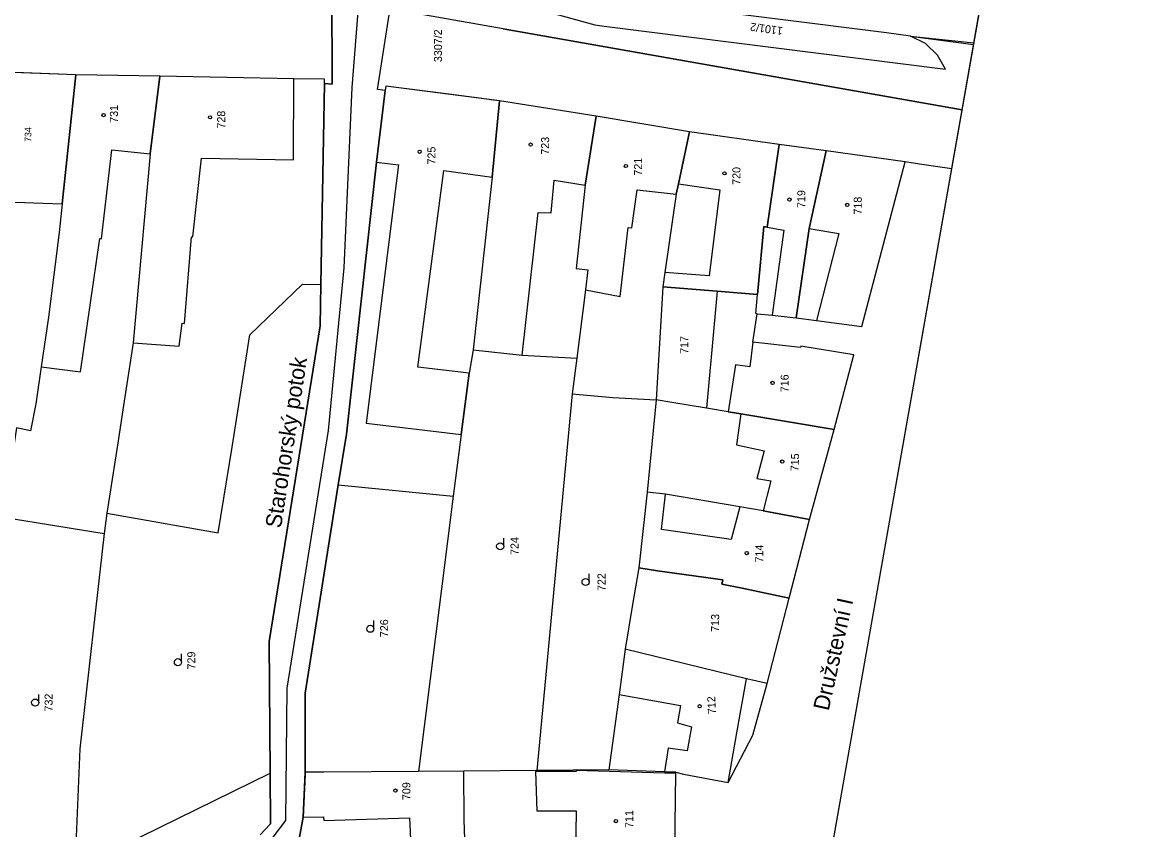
# Model space of a CAD drawing. Extents: x -534481 to -534262, y -1190577 to -1190138.
# Drawn here: x -534379.7 to -534261.7, y -1190343.4 to -1190257.6 of the extents above; entities that cross this region are included whole.
import ezdxf

# ---------------------------------------------------------------- set-up
doc = ezdxf.new("R2010")
doc.units = 0
for name, color, linetype in [('_KN_Povodí_Moravy', 7, 'Continuous'), ('_N_osa', 7, 'Continuous'), ('_rámeček', 7, 'Continuous'), ('_rámeček_mřížka', 7, 'Continuous'), ('Hranice parcel', 7, 'Continuous'), ('Parcelní čísla', 7, 'Continuous'), ('Polygon budovy', 7, 'Continuous'), ('Pop  PČ popisy', 7, 'Continuous'), ('Značky budov', 7, 'Continuous'), ('Značky kultur', 7, 'Continuous')]:
    doc.layers.add(name, color=color, linetype=linetype)

msp = doc.modelspace()

# ---------------------------------------------------------------- linework, layer by layer
at = {"layer": '_KN_Povodí_Moravy'}
msp.add_line((-534347.63, -1190264.06), (-534348.02, -1190285.43), dxfattribs=at)
for points in [[(-534346.75, -1190251.25), (-534346.86, -1190254.17), (-534346.83, -1190264.15), (-534347.63, -1190264.06)], [(-534341.18, -1190264.8), (-534341.99, -1190264.71), (-534340.47, -1190254.93), (-534340.33, -1190252.09)], [(-534346.16, -1190306.72), (-534345.3, -1190301.34), (-534342.09, -1190272.42), (-534341.18, -1190264.8)], [(-534348.02, -1190285.43), (-534348.1, -1190289.81), (-534353.51, -1190323.36), (-534353.4, -1190337.34)], [(-534349.69, -1190337.24), (-534349.7, -1190328.83), (-534346.16, -1190306.72)], [(-534353.09, -1190348.56), (-534350.53, -1190345.48), (-534349.9, -1190342.02), (-534349.69, -1190337.24)], [(-534353.4, -1190337.34), (-534353.36, -1190342.74), (-534354.46, -1190343.91)]]:
    msp.add_lwpolyline(points, dxfattribs=at)
at = {"layer": '_N_osa'}
for points in [[(-534344.68, -1190264.49), (-534342.94, -1190242.55)], [(-534409.87, -1190391.44), (-534405.95, -1190382.82), (-534400.87, -1190377.49), (-534393.7, -1190372.72), (-534384.93, -1190365.48), (-534382.63, -1190361.15), (-534355.89, -1190347.82), (-534351.74, -1190342.39), (-534351.58, -1190328.32), (-534347.2, -1190300.92), (-534345.55, -1190283.64), (-534344.68, -1190264.49)]]:
    msp.add_lwpolyline(points, dxfattribs=at)
at = {"layer": '_rámeček'}
for p, q in [((-534279.9, -1190266.87), (-534261.67, -1190163.46)), ((-534298.13, -1190370.27), (-534279.9, -1190266.87))]:
    msp.add_line(p, q, dxfattribs=at)
for points in [[(-534407.91, -1190137.67), (-534480.84, -1190551.29), (-534334.6, -1190577.08), (-534261.67, -1190163.46)], [(-534328.65, -1190258.27), (-534426.15, -1190241.08), (-534444.38, -1190344.48), (-534298.13, -1190370.27)], [(-534328.65, -1190258.27), (-534279.9, -1190266.87)], [(-534279.9, -1190266.87), (-534328.65, -1190258.27)]]:
    msp.add_lwpolyline(points, dxfattribs=at)
at = {"layer": '_rámeček_mřížka'}
msp.add_line((-534282.86, -1190266.34), (-534279.9, -1190266.87), dxfattribs=at)
msp.add_lwpolyline([(-534480.84, -1190551.29), (-534334.6, -1190577.08), (-534261.67, -1190163.46)], dxfattribs=at)
at = {"layer": 'Hranice parcel'}
for p, q in [((-534374.06, -1190263.13), (-534382.71, -1190262.81)), ((-534365.11, -1190263.3), (-534374.06, -1190263.13)), ((-534348.02, -1190285.43), (-534347.63, -1190264.06)), ((-534318.76, -1190267.54), (-534329.03, -1190265.92)), ((-534308.86, -1190269.19), (-534318.76, -1190267.54)), ((-534299.34, -1190270.54), (-534308.86, -1190269.19)), ((-534294.34, -1190271.21), (-534299.34, -1190270.54)), ((-534285.95, -1190272.39), (-534294.34, -1190271.21)), ((-534311.69, -1190285.66), (-534312.39, -1190297.68)), ((-534305.91, -1190286.14), (-534311.69, -1190285.66)), ((-534305.91, -1190286.14), (-534306.23, -1190289.63)), ((-534301.62, -1190286.49), (-534305.91, -1190286.14)), ((-534306.23, -1190289.63), (-534307.05, -1190298.57)), ((-534321.31, -1190297.03), (-534325.09, -1190337.06)), ((-534312.39, -1190297.68), (-534313.35, -1190307.49)), ((-534296.1, -1190310.4), (-534293.5, -1190300.81)), ((-534346.16, -1190306.72), (-534333.95, -1190307.91)), ((-534313.35, -1190307.49), (-534314.25, -1190315.51)), ((-534333.95, -1190307.91), (-534337.65, -1190337.15)), ((-534370.75, -1190309.73), (-534371.05, -1190311.86)), ((-534381.75, -1190310.15), (-534371.05, -1190311.86)), ((-534298.26, -1190318.76), (-534296.1, -1190310.4)), ((-534300.61, -1190327.81), (-534298.26, -1190318.76)), ((-534332.83, -1190337.12), (-534337.65, -1190337.15)), ((-534325.09, -1190337.06), (-534332.83, -1190337.12)), ((-534317.41, -1190337), (-534325.09, -1190337.06)), ((-534374.14, -1190347.51), (-534353.4, -1190337.34))]:
    msp.add_line(p, q, dxfattribs=at)
for points in [[(-534347.63, -1190264.06), (-534346.83, -1190264.15), (-534346.86, -1190254.17), (-534346.75, -1190251.25)], [(-534341.18, -1190264.8), (-534341.99, -1190264.71), (-534340.47, -1190254.93), (-534340.33, -1190252.09)], [(-534328.28, -1190255.25), (-534318.9, -1190257.84), (-534317.93, -1190257.96), (-534281.65, -1190262.55), (-534282.51, -1190261.06), (-534283.8, -1190259.83), (-534285.39, -1190259.03)], [(-534285.39, -1190259.03), (-534287.93, -1190258.69), (-534311.1, -1190255.76)], [(-534285.39, -1190259.03), (-534278.68, -1190259.92)], [(-534285.39, -1190259.03), (-534278.65, -1190259.74)], [(-534374.06, -1190263.13), (-534375.5, -1190276.84), (-534375.82, -1190279.89), (-534376.96, -1190288.9), (-534377.73, -1190294.18), (-534378.22, -1190297.6), (-534378.27, -1190297.93), (-534378.86, -1190300.97), (-534380.33, -1190300.65), (-534380.94, -1190304.74), (-534381.36, -1190307.53), (-534381.75, -1190310.15)], [(-534365.11, -1190263.3), (-534366.14, -1190271.54), (-534367.96, -1190291.63), (-534368.98, -1190298.28), (-534369.63, -1190302.5), (-534370.75, -1190309.73)], [(-534347.63, -1190264.06), (-534347.63, -1190263.6), (-534350.88, -1190263.57), (-534365.11, -1190263.3)], [(-534341.18, -1190264.8), (-534342.09, -1190272.42), (-534345.3, -1190301.34), (-534346.16, -1190306.72)], [(-534329.03, -1190265.92), (-534341.12, -1190264.34), (-534341.18, -1190264.8)], [(-534329.03, -1190265.92), (-534329.83, -1190274.01), (-534331.85, -1190292.36)], [(-534329.03, -1190265.92), (-534330.01, -1190265.79)], [(-534318.76, -1190267.54), (-534319.95, -1190274.86), (-534320.89, -1190283.73), (-534319.66, -1190283.86), (-534319.92, -1190285.99), (-534320.83, -1190293.25)], [(-534308.86, -1190269.19), (-534310.04, -1190274.74), (-534310.28, -1190275.84), (-534311.47, -1190284.16), (-534311.69, -1190285.66)], [(-534299.34, -1190270.54), (-534300.62, -1190279.32), (-534300.98, -1190279.26), (-534301.62, -1190286.49)], [(-534294.34, -1190271.21), (-534296.16, -1190279.48), (-534297.54, -1190288.96)], [(-534297.54, -1190288.96), (-534295.37, -1190289.25), (-534290.54, -1190289.89), (-534285.95, -1190272.39)], [(-534281.01, -1190273.14), (-534282, -1190272.99), (-534284.44, -1190272.62), (-534285.95, -1190272.39)], [(-534370.75, -1190309.73), (-534358.94, -1190311.81), (-534357.43, -1190302.69), (-534355.55, -1190290.76), (-534349.96, -1190285.37), (-534348.02, -1190285.43)], [(-534353.4, -1190337.34), (-534353.51, -1190323.36), (-534348.1, -1190289.81), (-534348.02, -1190285.43)], [(-534301.66, -1190288.52), (-534301.8, -1190288.5), (-534301.62, -1190286.49)], [(-534293.5, -1190300.81), (-534291.39, -1190292.89), (-534297.04, -1190291.98), (-534297.07, -1190292.12), (-534302.14, -1190291.55), (-534301.66, -1190288.52)], [(-534301.66, -1190288.52), (-534300.07, -1190288.69), (-534297.54, -1190288.96)], [(-534331.85, -1190292.36), (-534332.25, -1190294.85), (-534333.12, -1190301.37), (-534333.95, -1190307.91)], [(-534331.85, -1190292.36), (-534326.64, -1190292.92), (-534320.83, -1190293.25)], [(-534320.83, -1190293.25), (-534320.97, -1190294.31), (-534321.31, -1190297.03)], [(-534321.31, -1190297.03), (-534317.01, -1190297.41), (-534312.39, -1190297.68)], [(-534307.05, -1190298.57), (-534310.73, -1190297.96), (-534312.39, -1190297.68)], [(-534293.5, -1190300.81), (-534303.4, -1190299.17), (-534304.76, -1190298.94), (-534307.05, -1190298.57)], [(-534346.16, -1190306.72), (-534349.7, -1190328.83), (-534349.69, -1190337.24)], [(-534296.1, -1190310.4), (-534301.05, -1190309.46), (-534303.52, -1190309.04), (-534311.4, -1190307.7), (-534313.35, -1190307.49)], [(-534371.05, -1190311.86), (-534373.6, -1190334.76), (-534374.14, -1190347.51)], [(-534314.25, -1190315.51), (-534314.94, -1190319.65), (-534315.69, -1190324.17)], [(-534298.26, -1190318.76), (-534303.28, -1190317.7), (-534305.42, -1190317.25), (-534305.33, -1190316.8), (-534312.25, -1190315.85), (-534314.25, -1190315.51)], [(-534315.69, -1190324.17), (-534316.34, -1190328.99), (-534317.41, -1190337)], [(-534300.61, -1190327.81), (-534302.8, -1190327.32), (-534315.69, -1190324.17)], [(-534310.32, -1190337.25), (-534309.51, -1190337.45), (-534304.75, -1190338.32), (-534302.13, -1190333.32), (-534300.61, -1190327.81)], [(-534349.69, -1190337.24), (-534349.69, -1190337.44), (-534349.9, -1190342.02), (-534350.53, -1190345.48), (-534353.09, -1190348.56)], [(-534337.65, -1190337.15), (-534347.69, -1190337.23), (-534349.69, -1190337.24)], [(-534332.53, -1190349.48), (-534332.78, -1190342.31), (-534332.83, -1190337.12)], [(-534310.32, -1190337.25), (-534311.5, -1190337.21), (-534317.41, -1190337)], [(-534315.73, -1190352.48), (-534310.81, -1190348.3), (-534310.45, -1190348.3), (-534310.32, -1190337.38), (-534310.32, -1190337.25)], [(-534354.46, -1190343.91), (-534353.36, -1190342.74), (-534353.4, -1190337.34)]]:
    msp.add_lwpolyline(points, dxfattribs=at)
at = {"layer": 'Polygon budovy'}
for points in [[(-534382.71, -1190262.81), (-534383.47, -1190268.46), (-534384.56, -1190276.52), (-534375.5, -1190276.84), (-534374.06, -1190263.13)], [(-534377.73, -1190294.18), (-534373.53, -1190294.69), (-534371.48, -1190280.54), (-534371.33, -1190280.57), (-534370.23, -1190271.12), (-534366.14, -1190271.54), (-534365.11, -1190263.3), (-534374.06, -1190263.13), (-534375.5, -1190276.84), (-534375.82, -1190279.89), (-534376.96, -1190288.9)], [(-534366.14, -1190271.54), (-534367.96, -1190291.63), (-534363.08, -1190291.98), (-534362.74, -1190289.52), (-534362.49, -1190289.56), (-534361.74, -1190280.34), (-534361.6, -1190280.35), (-534360.7, -1190271.99), (-534350.93, -1190272.19), (-534350.88, -1190263.57), (-534365.11, -1190263.3)], [(-534329.03, -1190265.92), (-534329.83, -1190274.01), (-534331.85, -1190292.36), (-534326.64, -1190292.92), (-534324.94, -1190277.76), (-534323.57, -1190277.82), (-534323.23, -1190274.35), (-534319.95, -1190274.86), (-534318.76, -1190267.54)], [(-534319.92, -1190285.99), (-534316.22, -1190286.71), (-534315.36, -1190279.35), (-534314.97, -1190279.41), (-534314.43, -1190275.35), (-534310.28, -1190275.84), (-534310.04, -1190274.74), (-534308.86, -1190269.19), (-534318.76, -1190267.54), (-534319.95, -1190274.86), (-534320.89, -1190283.73), (-534319.66, -1190283.86)], [(-534311.69, -1190285.66), (-534305.91, -1190286.14), (-534301.62, -1190286.49), (-534300.98, -1190279.26), (-534300.62, -1190279.32), (-534299.34, -1190270.54), (-534308.86, -1190269.19), (-534310.04, -1190274.74), (-534305.65, -1190275.36), (-534306.77, -1190284.49), (-534311.47, -1190284.16)], [(-534300.07, -1190288.69), (-534297.54, -1190288.96), (-534296.16, -1190279.48), (-534294.34, -1190271.21), (-534299.34, -1190270.54), (-534300.62, -1190279.32), (-534298.85, -1190279.64)], [(-534295.37, -1190289.25), (-534290.54, -1190289.89), (-534285.95, -1190272.39), (-534294.34, -1190271.21), (-534296.16, -1190279.48), (-534293, -1190280.01)], [(-534302.14, -1190291.55), (-534302.44, -1190294.18), (-534303.96, -1190293.94), (-534304.76, -1190298.94), (-534303.4, -1190299.17), (-534293.5, -1190300.81), (-534291.39, -1190292.89), (-534297.04, -1190291.98), (-534297.07, -1190292.12)], [(-534301.7, -1190306.03), (-534300.21, -1190306.28), (-534301.05, -1190309.46), (-534296.1, -1190310.4), (-534293.5, -1190300.81), (-534303.4, -1190299.17), (-534303.85, -1190302.47), (-534300.92, -1190303.1)], [(-534314.25, -1190315.51), (-534312.25, -1190315.85), (-534305.33, -1190316.8), (-534305.42, -1190317.25), (-534303.28, -1190317.7), (-534298.26, -1190318.76), (-534296.1, -1190310.4), (-534301.05, -1190309.46), (-534303.52, -1190309.04), (-534304.43, -1190312.52), (-534311.84, -1190311.46), (-534311.4, -1190307.7), (-534313.35, -1190307.49)], [(-534310.13, -1190332), (-534308.64, -1190332.42), (-534309.09, -1190334.97), (-534311.12, -1190334.7), (-534311.5, -1190337.21), (-534310.32, -1190337.25), (-534309.51, -1190337.45), (-534304.75, -1190338.32), (-534303.82, -1190333.06), (-534302.8, -1190327.32), (-534315.69, -1190324.17), (-534316.34, -1190328.99), (-534309.81, -1190330.15)], [(-534349.9, -1190342.02), (-534347.72, -1190341.99), (-534347.71, -1190342.39), (-534338.59, -1190342.1), (-534338.12, -1190352.66), (-534336.88, -1190352.6), (-534336.67, -1190354.99), (-534334.35, -1190354.21), (-534332.65, -1190353.81), (-534332.6, -1190352.16), (-534332.53, -1190349.48), (-534332.78, -1190342.31), (-534332.83, -1190337.12), (-534337.65, -1190337.15), (-534347.69, -1190337.23), (-534349.69, -1190337.24), (-534349.69, -1190337.44)], [(-534320.89, -1190337.07), (-534320.88, -1190337.18), (-534325.2, -1190337.17), (-534325.09, -1190341.34), (-534320.9, -1190341.35), (-534320.99, -1190348.17), (-534318.18, -1190348.21), (-534317.67, -1190349.12), (-534315.85, -1190349.15), (-534315.3, -1190348.25), (-534310.81, -1190348.3), (-534310.45, -1190348.3), (-534310.32, -1190337.38)]]:
    msp.add_lwpolyline(points, close=True, dxfattribs=at)
msp.add_lwpolyline([(-534334.43, -1190265.21), (-534341.12, -1190264.34), (-534341.18, -1190264.8), (-534342.09, -1190272.42), (-534339.77, -1190272.69), (-534343.2, -1190300.17), (-534333.12, -1190301.37), (-534332.25, -1190294.85), (-534337.72, -1190294.22), (-534334.94, -1190273.31), (-534329.83, -1190274.01), (-534329.03, -1190265.92), (-534334.43, -1190265.21)], dxfattribs=at)
at = {"layer": 'Značky budov'}
for centre in [(-534371.09, -1190267.42), (-534359.79, -1190267.66), (-534337.52, -1190271.32), (-534325.73, -1190270.56), (-534315.62, -1190272.83), (-534305.15, -1190273.61), (-534298.25, -1190276.39), (-534292.11, -1190276.96), (-534300.03, -1190295.88), (-534299.01, -1190304.23), (-534302.77, -1190313.96), (-534307.78, -1190330.23), (-534340.09, -1190339.19), (-534316.67, -1190342.44)]:
    msp.add_circle(centre, 0.175, dxfattribs=at)
at = {"layer": 'Značky kultur'}
for p, q in [((-534328.59, -1190313.24), (-534328.59, -1190312.36)), ((-534319.53, -1190317.03), (-534319.53, -1190316.15)), ((-534342.39, -1190322), (-534342.39, -1190321.13)), ((-534362.82, -1190325.55), (-534362.82, -1190324.68)), ((-534377.99, -1190329.84), (-534377.99, -1190328.97))]:
    msp.add_line(p, q, dxfattribs=at)
for centre in [(-534328.97, -1190313.24), (-534319.9, -1190317.03), (-534342.76, -1190322), (-534363.2, -1190325.55), (-534378.36, -1190329.84)]:
    msp.add_circle(centre, 0.375, dxfattribs=at)

# ---------------------------------------------------------------- texts
at = {"layer": 'Parcelní čísla'}
for s, height, rotation, p in [('1101/2', 0.85, 172, (-534298.9, -1190258.09)), ('3307/2', 0.85, 90, (-534335.15, -1190261.79)), ('731', 0.85, 90, (-534369.57, -1190268.24)), ('728', 0.85, 90, (-534358.18, -1190268.85)), ('734', 0.7, 90, (-534378.77, -1190270.27)), ('723', 0.85, 90, (-534323.77, -1190271.63)), ('725', 0.85, 90, (-534335.84, -1190272.67)), ('721', 0.85, 90, (-534313.9, -1190273.85)), ('720', 0.85, 90, (-534303.45, -1190274.83)), ('719', 0.85, 90, (-534296.56, -1190277.29)), ('718', 0.85, 90, (-534290.56, -1190277.99)), ('717', 0.85, 90, (-534308.99, -1190292.79)), ('716', 0.85, 90, (-534298.33, -1190296.87)), ('715', 0.85, 88, (-534297.28, -1190305.28)), ('724', 0.85, 90, (-534327.02, -1190314.16)), ('714', 0.85, 90, (-534301.02, -1190314.96)), ('722', 0.85, 90, (-534317.78, -1190317.99)), ('713', 0.85, 90, (-534305.71, -1190322.33)), ('726', 0.85, 90, (-534340.87, -1190322.89)), ('729', 0.85, 90, (-534361.35, -1190326.32)), ('732', 0.85, 90, (-534376.51, -1190330.79)), ('712', 0.85, 93, (-534306.04, -1190331.05)), ('709', 0.85, 90, (-534338.51, -1190340.2)), ('711', 0.85, 90, (-534314.84, -1190343.16))]:
    msp.add_text(s, height=height, rotation=rotation, dxfattribs=at).set_placement(p)
at = {"layer": 'Pop  PČ popisy'}
for s, rotation, p in [('Starohorský potok', 81.2569, (-534352.25, -1190311.38)), ('Družstevní I', 77.5156, (-534294.08, -1190330.79))]:
    msp.add_text(s, height=1.7, rotation=rotation, dxfattribs=at).set_placement(p)

doc.saveas('drawing.dxf')
